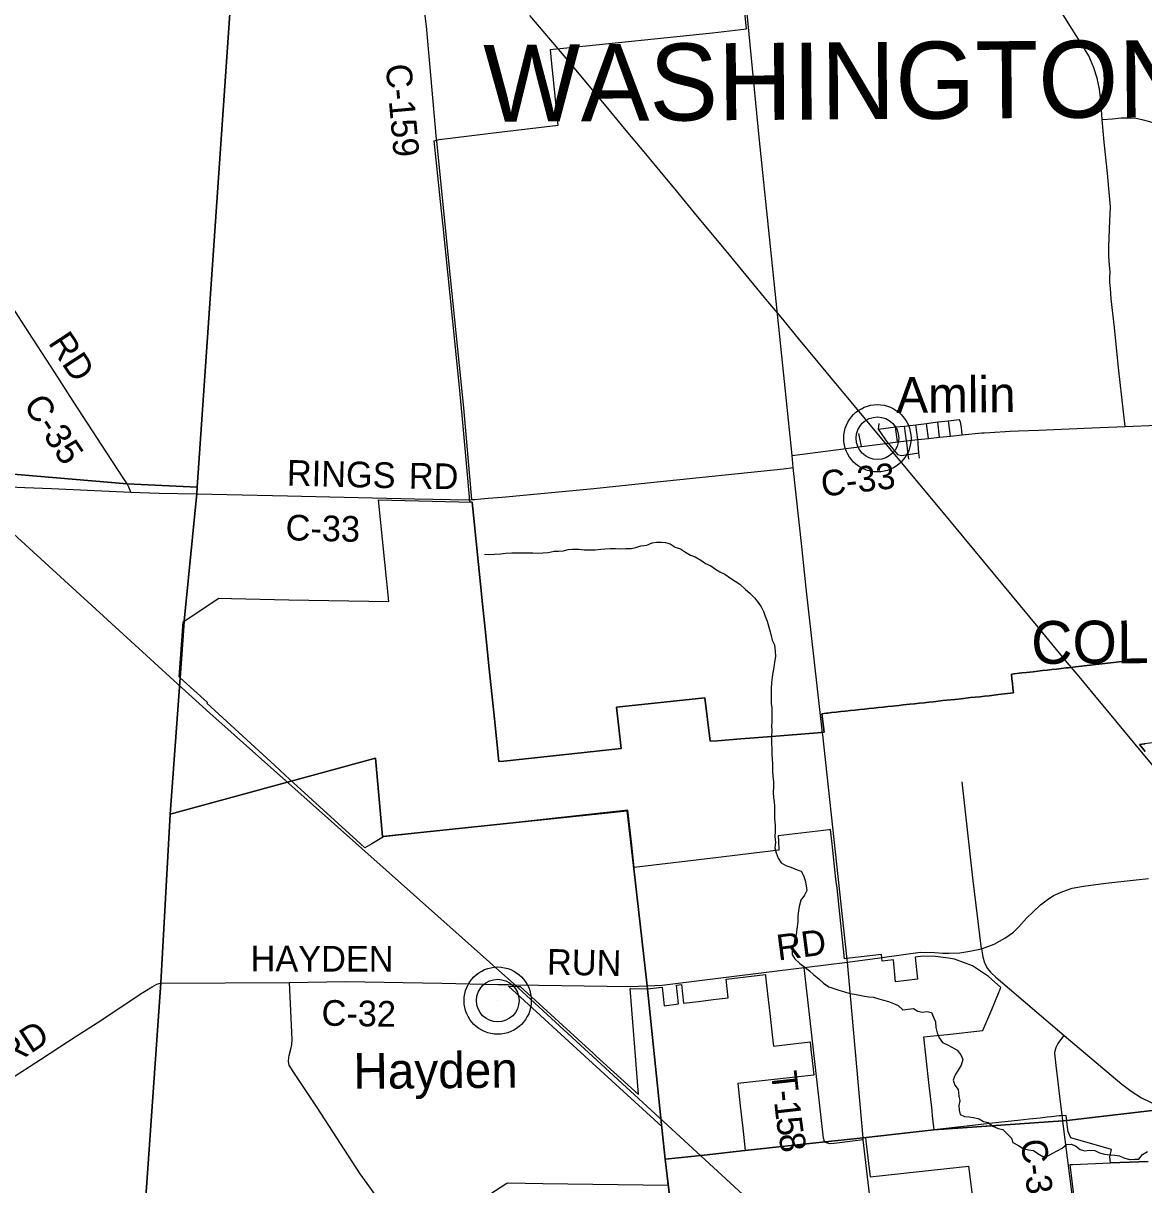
# Model space of a CAD drawing. Extents: x 114843 to 284848, y 317643 to 566895.
# Drawn here: x 145352 to 158450, y 419999 to 433575 of the extents above; entities that cross this region are included whole.
import ezdxf

# ---------------------------------------------------------------- set-up
doc = ezdxf.new("R2010")
doc.units = 0
for name, color, linetype in [('GM_X_City_Street', 7, 'Continuous'), ('GM_X_Corporation', 7, 'Continuous'), ('GM_X_Corporation_Text', 7, 'Continuous'), ('GM_X_County', 7, 'Continuous'), ('GM_X_County_Road', 7, 'Continuous'), ('GM_X_County_Road_Text', 7, 'Continuous'), ('GM_X_Minor_River', 7, 'Continuous'), ('GM_X_Rail_Line', 7, 'Continuous'), ('GM_X_Township', 7, 'Continuous'), ('GM_X_Township_Road', 7, 'Continuous'), ('GM_X_Township_Road_Text', 7, 'Continuous'), ('GM_X_Township_Text', 7, 'Continuous'), ('GM_X_Unincorporated', 7, 'Continuous'), ('GM_X_Unincorporated_Location', 7, 'Continuous'), ('GM_X_Unincorporated_Text', 7, 'Continuous')]:
    doc.layers.add(name, color=color, linetype=linetype)

msp = doc.modelspace()

# ---------------------------------------------------------------- linework, layer by layer
at = {"layer": 'GM_X_City_Street'}
for points in [[(158233, 428861), (158155, 429548), (158106, 430017), (158069, 430354), (158059, 430474), (158054, 430546), (158055, 430600), (158058, 430669), (158051, 430748), (158040, 430854), (158042, 430967), (158054, 431267), (158059, 431429), (158041, 431644), (158026, 431821), (157988, 432183), (157965, 432449), (157946, 432673), (157931, 432805), (157905, 432934), (157867, 433053), (157806, 433193), (157705, 433356), (157613, 433505), (157373, 433894)], [(157965, 432449), (158086, 432459), (158184, 432470), (158255, 432470), (158301, 432469), (158362, 432464), (158427, 432449), (158515, 432427), (158603, 432395), (158736, 432329), (158821, 432262), (158879, 432210), (158886, 432202)], [(156554, 422758), (156452, 423586), (156326, 424708)], [(156554, 422758), (156703, 422811), (156827, 422882), (156926, 422952), (156988, 423012), (157082, 423120), (157155, 423188), (157243, 423271), (157321, 423330), (157396, 423379), (157505, 423428), (157614, 423466), (157745, 423487), (158007, 423522), (158362, 423562), (158504, 423577)]]:
    msp.add_lwpolyline(points, dxfattribs=at)
at = {"layer": 'GM_X_Corporation'}
for points in [[(158460, 426143), (158233, 426117), (157651, 426052), (157570, 426042), (157541, 426039), (157486, 426033), (157431, 426026), (157377, 426020), (157322, 426014), (157267, 426008), (157213, 426002), (157158, 425995), (157078, 425986), (157026, 425981), (156902, 425966), (156908, 425912), (156914, 425857), (156920, 425802), (156926, 425747), (156753, 425727), (156698, 425721), (156643, 425715), (156589, 425709), (156534, 425703), (156479, 425698), (156425, 425692), (156370, 425686), (156315, 425680), (156241, 425672), (156189, 425666), (156100, 425657), (156045, 425651), (155990, 425645), (155936, 425639), (155881, 425633), (155826, 425627), (155771, 425621), (155717, 425616), (155638, 425607), (155587, 425602), (155512, 425594), (155457, 425588), (155403, 425582), (155348, 425576), (155293, 425570), (155239, 425564), (155184, 425558), (155129, 425552), (155075, 425547), (155020, 425541), (154965, 425535), (154910, 425529), (154856, 425523), (154801, 425517), (154756, 425512), (154740, 425511), (154687, 425502), (154714, 425290), (154636, 425282), (154102, 425239), (153739, 425210), (153467, 425188), (153382, 425182), (153320, 425689), (152288, 425580), (152341, 425096), (150969, 424951), (150911, 424945), (150860, 425443), (150800, 426027), (150752, 426494), (150722, 426787), (150600, 427978), (150573, 427979), (150567, 428039), (150482, 428992), (150452, 429321), (150259, 431203), (150230, 431490), (150187, 431904), (150157, 432201), (150215, 432217), (150915, 432300), (151603, 432383), (151581, 432609), (151557, 432841), (151528, 433139), (151515, 433269), (151546, 433272), (151668, 433283), (153407, 433464), (153807, 433508), (153757, 434016)], [(158502, 420272), (158061, 420254), (158052, 420325), (158072, 420411), (157597, 420549), (157565, 420618), (157558, 420673), (157541, 420810), (157479, 420805), (157459, 420803), (157370, 420793), (157320, 420787), (157239, 420779), (157112, 420764), (156977, 420749), (156715, 420721), (156345, 420680), (156000, 420641), (155985, 420771), (155971, 420901), (155957, 421030), (155943, 421160), (155908, 421477), (155880, 421726), (155992, 421738), (156153, 421756), (156569, 421801), (156626, 421939), (156672, 422049), (156778, 422305), (156633, 422432), (156446, 422557), (156237, 422636), (156167, 422647), (156014, 422666), (155873, 422669), (155779, 422658), (155806, 422401), (155546, 422369), (155523, 422627), (155393, 422612), (155383, 422691), (155010, 422646), (154951, 422640), (154864, 423465), (154852, 423570), (154807, 423983), (154788, 424150), (154774, 424149), (154177, 424078), (154180, 424018), (154186, 423908), (153734, 423854), (153477, 423823), (152493, 423708), (152460, 424006), (152419, 424378), (151431, 424268), (150974, 424217), (149562, 424064), (149427, 423984), (149345, 423935), (149293, 423983), (148470, 424734), (148292, 424898), (147497, 425627), (147504, 425635), (147187, 425925), (147174, 425936), (147223, 426577), (147640, 426855), (147788, 426852), (148455, 426836), (149625, 426814), (149504, 428003), (150600, 427978), (150722, 426787), (150752, 426494), (150800, 426027), (150860, 425443), (150911, 424945), (150969, 424951), (152341, 425096), (152288, 425580), (153320, 425689), (153382, 425182), (153467, 425188), (153739, 425210), (154102, 425239), (154636, 425282), (154714, 425290), (154687, 425502), (154740, 425511), (154756, 425512), (154801, 425517), (154856, 425523), (154910, 425529), (154965, 425535), (155020, 425541), (155075, 425547), (155129, 425552), (155184, 425558), (155239, 425564), (155293, 425570), (155348, 425576), (155403, 425582), (155457, 425588), (155512, 425594), (155587, 425602), (155638, 425607), (155717, 425616), (155771, 425621), (155826, 425627), (155881, 425633), (155936, 425639), (155964, 425642), (155990, 425645), (156045, 425651), (156100, 425657), (156189, 425666), (156241, 425672), (156315, 425680), (156370, 425686), (156425, 425692), (156479, 425698), (156534, 425703), (156589, 425709), (156643, 425715), (156698, 425721), (156753, 425727), (156926, 425747), (156920, 425802), (156914, 425857), (156908, 425912), (156902, 425966), (157026, 425981), (157078, 425986), (157158, 425995), (157213, 426002), (157267, 426008), (157322, 426014), (157377, 426020), (157431, 426026), (157486, 426033), (157541, 426039), (157570, 426042), (157651, 426052), (158233, 426117), (158460, 426143)], [(158879, 425207), (158400, 425145), (158468, 425063)], [(158468, 425063), (158400, 425145), (158467, 425154)], [(150354, 419596), (151004, 420017), (151013, 420023), (151425, 420015), (152891, 419993), (152819, 420668), (152817, 420681), (151917, 421502), (151024, 422318), (151135, 422316), (151160, 422316), (152013, 421536), (152050, 421503), (152544, 421052), (152507, 421506), (152446, 422293), (152647, 422289), (152821, 422310), (152844, 422090), (153011, 422113), (152989, 422331), (153048, 422338), (153070, 422120), (153245, 422142), (153418, 422163), (153488, 422171), (153593, 422184), (153570, 422401), (154027, 422456), (154029, 422437), (154052, 422230), (154078, 422001), (154107, 421751), (154121, 421620), (154549, 421668), (154563, 421539), (154565, 421521), (154592, 421278), (154163, 421231), (153703, 421181), (153732, 420920), (153762, 420660), (153791, 420399), (154677, 420496), (154764, 420506), (154925, 420523), (155100, 420544), (155196, 420553), (155205, 420472), (155212, 420413), (155224, 420314), (155250, 420090), (156003, 420173), (156402, 420215), (156459, 419755)], [(157634, 419882), (157590, 420234), (157622, 420235), (158061, 420254), (158502, 420272)]]:
    msp.add_lwpolyline(points, dxfattribs=at)
at = {"layer": 'GM_X_County'}
for points in [[(146658, 418022), (146962, 422359), (147068, 424330), (147186, 425925), (147235, 426587), (147381, 428077), (147386, 428151), (148148, 439230), (148177, 439983), (151138, 439882), (152473, 439858), (155550, 439725), (156053, 439712), (156142, 439709), (156715, 439694), (157545, 439673), (158384, 439650), (158384, 439701), (158353, 446272), (158350, 446686), (158334, 448459), (158404, 452871)], [(140707, 440166), (147260, 440014), (148177, 439983), (148148, 439230), (147386, 428151), (147381, 428077), (147235, 426587), (147186, 425925), (147068, 424330), (146962, 422359), (146658, 418022)]]:
    msp.add_lwpolyline(points, dxfattribs=at)
at = {"layer": 'GM_X_County_Road'}
for p, q in [((154351, 428382), (154338, 428524)), ((154987, 422600), (155366, 422653)), ((146963, 422356), (148463, 422362))]:
    msp.add_line(p, q, dxfattribs=at)
for points in [[(150183, 432219), (150065, 433541), (149938, 434551), (149800, 435349), (149768, 435758), (149550, 438468), (149481, 439320)], [(146567, 428190), (146545, 428225), (146526, 428251), (146331, 428554), (145936, 429157), (145721, 429491), (145366, 430037), (145064, 430505), (144797, 430918), (144567, 431276), (144032, 432101), (143429, 433037), (143149, 433468), (142166, 434991), (142073, 435132), (141863, 435459), (141131, 436585), (140458, 437632), (140407, 437716), (140358, 437803)], [(154338, 428524), (153953, 432244), (153783, 434012), (153716, 434749), (153493, 435495), (153393, 435859), (153264, 436358), (153244, 436435)], [(150596, 428008), (150502, 429081), (150348, 430601), (150185, 432198), (150183, 432219)], [(156586, 428789), (156649, 428793), (156888, 428808), (156987, 428811), (157222, 428819), (157844, 428845), (158233, 428861), (158601, 428875), (158644, 428876), (158689, 428875), (158767, 428869), (159043, 428845), (159121, 428839), (159523, 428805), (159868, 428775), (159950, 428767), (160013, 428766), (160060, 428768), (160463, 428804), (160701, 428825), (161086, 428857), (161867, 428926)], [(154338, 428524), (155149, 428628), (155461, 428665), (155571, 428681), (155676, 428693), (155808, 428708), (155935, 428722), (156061, 428736), (156190, 428749), (156326, 428763), (156555, 428787), (156586, 428789)], [(150700, 428015), (150788, 428022), (150950, 428037), (152021, 428135), (152723, 428211), (154240, 428368), (154351, 428382)], [(154697, 425258), (154694, 425278), (154504, 426972), (154451, 427460), (154351, 428382)], [(141611, 427895), (141926, 427922), (141949, 427922), (142074, 427935), (142172, 427943), (142241, 427946), (143106, 428018), (144362, 428129), (144738, 428163), (144822, 428167), (145001, 428163), (145372, 428148), (145683, 428137), (146608, 428095)], [(146608, 428095), (146596, 428132), (146587, 428152), (146567, 428190)], [(146608, 428095), (146940, 428082), (147383, 428074)], [(147383, 428074), (148441, 428051), (149931, 428016), (150557, 428005), (150596, 428008), (150627, 428009), (150700, 428015)], [(154980, 422652), (154978, 422666), (154697, 425258)], [(155171, 420524), (155169, 420546), (154987, 422600), (154983, 422633), (154980, 422652)], [(155366, 422653), (155836, 422719), (156003, 422713), (156102, 422704), (156176, 422706), (156300, 422711), (156415, 422729), (156554, 422758), (156568, 422664), (156590, 422591), (156624, 422528), (156660, 422482), (156722, 422426), (157518, 421745)], [(152641, 422322), (152647, 422322), (152820, 422333), (153569, 422426), (154479, 422538), (154987, 422600)], [(144135, 420538), (144393, 420703), (145193, 421230), (145555, 421461), (145779, 421611), (145960, 421726), (146217, 421893), (146749, 422246), (146858, 422313), (146914, 422343), (146955, 422356), (146963, 422356)], [(150949, 417965), (150944, 417982), (150930, 418008), (150891, 418068), (150181, 418971), (149524, 419805), (149292, 420128), (148786, 420900), (148506, 421321), (148462, 421397), (148451, 421440), (148455, 421485), (148461, 421510), (148481, 421582), (148493, 421640), (148495, 421698), (148463, 422362)], [(148463, 422362), (149120, 422376), (150245, 422355), (150902, 422339), (150999, 422339)], [(150999, 422339), (151020, 422338), (151105, 422337)], [(151105, 422337), (152445, 422317), (152641, 422322)], [(157430, 421356), (157410, 421537), (157413, 421566), (157420, 421591), (157429, 421616), (157446, 421647), (157518, 421745)], [(157518, 421745), (158193, 421174), (158301, 421094), (158423, 421015), (158527, 420963), (158619, 420922)], [(157499, 420783), (157468, 421029), (157437, 421299), (157430, 421356)], [(157617, 419842), (157613, 419874), (157611, 419885), (157505, 420741), (157499, 420783)], [(155356, 418905), (155352, 418962), (155171, 420524)]]:
    msp.add_lwpolyline(points, dxfattribs=at)
at = {"layer": 'GM_X_Minor_River'}
for points in [[(150745, 427368), (150803, 427366), (150861, 427370), (150935, 427373), (150991, 427381), (151065, 427384), (151121, 427386), (151175, 427384), (151239, 427385), (151307, 427385), (151359, 427381), (151425, 427386), (151489, 427390), (151559, 427403), (151611, 427405), (151667, 427407), (151722, 427424), (151774, 427426), (151846, 427426), (151908, 427421), (151966, 427421), (152038, 427418), (152102, 427426), (152152, 427430), (152212, 427435), (152276, 427435), (152336, 427431), (152394, 427436), (152460, 427436), (152514, 427448), (152572, 427465), (152640, 427473), (152702, 427501), (152754, 427508), (152808, 427510), (152860, 427504), (152914, 427491), (152974, 427451), (153034, 427430), (153092, 427394), (153151, 427359), (153207, 427339), (153271, 427298), (153325, 427260), (153389, 427232), (153442, 427193), (153494, 427163), (153552, 427136), (153620, 427090), (153674, 427055), (153727, 427019), (153793, 426958), (153847, 426914), (153898, 426859), (153942, 426805), (153978, 426755), (154004, 426700), (154023, 426646), (154047, 426588), (154076, 426489), (154096, 426419), (154106, 426365), (154135, 426310), (154141, 426236), (154144, 426174), (154132, 426108), (154124, 426046), (154115, 425987), (154107, 425933), (154097, 425869), (154096, 425797), (154094, 425725), (154093, 425623), (154103, 425572), (154101, 425520), (154102, 425464), (154102, 425410), (154098, 425360), (154103, 425308), (154099, 425239), (154098, 425161), (154102, 425091), (154102, 425031), (154105, 424973), (154111, 424918), (154111, 424832), (154114, 424776), (154120, 424710), (154121, 424648), (154119, 424585), (154123, 424527), (154128, 424475), (154132, 424423), (154132, 424361), (154135, 424276), (154141, 424200), (154140, 424126), (154138, 424068), (154146, 424000), (154139, 423935), (154153, 423877)], [(154153, 423877), (154177, 423817), (154212, 423760), (154266, 423730), (154324, 423712), (154378, 423689), (154444, 423663), (154471, 423612), (154491, 423556), (154503, 423494), (154510, 423438), (154484, 423382), (154442, 423324), (154425, 423268), (154413, 423206), (154407, 423137), (154406, 423075), (154394, 422985), (154385, 422919), (154367, 422859), (154359, 422803), (154340, 422749), (154338, 422691), (154372, 422638), (154431, 422584), (154487, 422543), (154541, 422501), (154592, 422452), (154650, 422404), (154706, 422355), (154770, 422313), (154828, 422294), (154887, 422274), (154939, 422256), (155015, 422235), (155067, 422225), (155127, 422214), (155185, 422202), (155237, 422196), (155289, 422191), (155351, 422173), (155407, 422158), (155467, 422140), (155523, 422116), (155578, 422093), (155632, 422043), (155696, 422050), (155758, 422060), (155810, 422026), (155862, 422015), (155914, 422025), (155970, 422013), (155990, 421958), (156017, 421904), (156019, 421836), (156035, 421773), (156060, 421715), (156098, 421661), (156156, 421634), (156214, 421604), (156267, 421573), (156311, 421517), (156335, 421463), (156316, 421395), (156280, 421337), (156246, 421285), (156223, 421221), (156243, 421164), (156281, 421114), (156288, 421034), (156298, 420978), (156290, 420925), (156293, 420871), (156303, 420819), (156355, 420797), (156409, 420792), (156461, 420784), (156525, 420768), (156576, 420737), (156630, 420725), (156684, 420684), (156746, 420658), (156802, 420646), (156854, 420593), (156905, 420545), (156919, 420494), (156987, 420456), (157039, 420421), (157101, 420405), (157159, 420401), (157212, 420364), (157270, 420330), (157330, 420337), (157380, 420363), (157439, 420397), (157495, 420427), (157547, 420468), (157601, 420474), (157653, 420454), (157707, 420411), (157761, 420397)], [(157761, 420397), (157821, 420403), (157879, 420398), (157932, 420372), (157990, 420357), (158052, 420347), (158110, 420345), (158166, 420338), (158218, 420314), (158282, 420295), (158340, 420299), (158392, 420299), (158436, 420351), (158495, 420388)]]:
    msp.add_lwpolyline(points, dxfattribs=at)
at = {"layer": 'GM_X_Rail_Line'}
for points in [[(128479, 440489), (130998, 439418), (131780, 439073), (132352, 438743), (133270, 438069), (136074, 435852), (137429, 434713), (140276, 432132), (143769, 428946), (146519, 426434), (147203, 425812)], [(159907, 423274), (158330, 425173), (158010, 425557), (157837, 425765), (157693, 425940), (157535, 426128), (157236, 426492), (156029, 427945), (155540, 428536), (155066, 429106), (154739, 429502), (154570, 429704), (154430, 429872), (154230, 430114), (154144, 430218), (154057, 430324), (154018, 430370), (153623, 430848), (153199, 431358), (152953, 431658), (152889, 431734), (152628, 432050), (152401, 432322), (152202, 432563), (151700, 433168), (151275, 433667)], [(147203, 425812), (147532, 425512), (151087, 422349), (154540, 419172), (158440, 415556), (161813, 412533), (168064, 407288)]]:
    msp.add_lwpolyline(points, dxfattribs=at)
at = {"layer": 'GM_X_Township'}
for points in [[(140707, 440166), (147260, 440014), (148177, 439983), (148148, 439230), (147386, 428151), (146566, 428193), (136882, 429015)], [(158583, 420870), (157550, 420750), (157503, 420744), (155996, 420640), (155168, 420549), (154726, 420500), (153787, 420398), (153312, 420346), (152854, 420299), (152815, 420666), (152645, 422325), (152484, 423731), (152411, 424370), (149551, 424070), (149471, 424984), (147068, 424330), (147186, 425925), (147235, 426587), (147381, 428077), (147386, 428151), (148148, 439230)], [(114843, 430764), (117844, 430522), (126052, 429792), (135272, 429152), (136882, 429015), (146566, 428193), (147386, 428151), (147381, 428077), (147235, 426587), (147186, 425925), (147068, 424330), (146962, 422359), (146658, 418022)], [(146658, 418022), (146962, 422359), (147068, 424330), (149471, 424984), (149551, 424070), (152411, 424370), (152484, 423731), (152645, 422325), (152815, 420666), (152854, 420299), (153740, 412913)], [(153740, 412913), (152854, 420299), (153312, 420346), (153787, 420398), (154726, 420500), (155168, 420549), (155996, 420640), (157503, 420744), (157550, 420750), (158583, 420870)]]:
    msp.add_lwpolyline(points, dxfattribs=at)
at = {"layer": 'GM_X_Township_Road'}
for p, q in [((155350, 428832), (155358, 428896)), ((155935, 428722), (155911, 428897)), ((156061, 428736), (156042, 428914)), ((156190, 428749), (156166, 428927)), ((155149, 428628), (155121, 428781)), ((155461, 428665), (155350, 428832)), ((155571, 428681), (155548, 428857))]:
    msp.add_line(p, q, dxfattribs=at)
for points in [[(155350, 428832), (155548, 428857), (155653, 428867), (155785, 428879), (155911, 428897), (156042, 428914), (156166, 428927), (156293, 428944)], [(155814, 428655), (155811, 428686), (155808, 428708), (155785, 428879)], [(156326, 428763), (156319, 428850), (156308, 428917), (156293, 428944)], [(155683, 428642), (155679, 428674), (155676, 428693), (155653, 428867)], [(155461, 428665), (155571, 428533), (155616, 428522), (155697, 428534), (155822, 428554)], [(155704, 428480), (155697, 428534), (155683, 428642)], [(155827, 428492), (155822, 428554), (155814, 428655)], [(154755, 420484), (154740, 420488), (154727, 420498), (154717, 420504), (154706, 420544), (154479, 422538)], [(155171, 420524), (154829, 420482), (154779, 420478), (154755, 420484)]]:
    msp.add_lwpolyline(points, dxfattribs=at)
at = {"layer": 'GM_X_Unincorporated'}
for centre, radius in [((155336, 428724), 393), ((155336, 428724), 249), ((150898, 422151), 393), ((150898, 422151), 249)]:
    msp.add_circle(centre, radius, dxfattribs=at)
at = {"layer": 'GM_X_Unincorporated_Location'}
for p, q in [((155336, 428724), (155336, 428724)), ((150898, 422151), (150898, 422151))]:
    msp.add_line(p, q, dxfattribs=at)

# ---------------------------------------------------------------- texts
at = {"layer": 'GM_X_Corporation_Text'}
msp.add_text('COLUMBUS', height=500, rotation=0.4122, dxfattribs=at).set_placement((157135, 426086))
at = {"layer": 'GM_X_County_Road_Text'}
for s, rotation, p in [('C-159', 275.1069, (149588, 433088)), ('RD', 303.2882, (145636, 429840)), ('C-35', 303.4357, (145346, 429113)), ('RINGS', 358.5792, (148431, 428171)), ('RD', 358.9503, (149857, 428137)), ('C-33', 6.7652, (154695, 428040)), ('C-33', 358.6966, (148416, 427532)), ('RD', 7.3531, (154177, 422619)), ('HAYDEN', 359.9233, (148009, 422492)), ('RUN', 358.873, (151472, 422455)), ('C-32', 359.0723, (148837, 421859)), ('RD', 33.1749, (145196, 421369)), ('C-37', 277.2824, (157011, 420515))]:
    msp.add_text(s, height=300, rotation=rotation, dxfattribs=at).set_placement(p)
at = {"layer": 'GM_X_Township_Road_Text'}
for s, rotation, p in [('T', 276.1257, (154092, 421314)), ('-', 276.1857, (154116, 421091)), ('1', 276.5047, (154129, 420967)), ('5', 277.5314, (154151, 420777)), ('8', 280.2486, (154178, 420579))]:
    msp.add_text(s, height=300, rotation=rotation, dxfattribs=at).set_placement(p)
at = {"layer": 'GM_X_Township_Text'}
msp.add_text('WASHINGTON', height=900, rotation=0.412, dxfattribs=at).set_placement((150734, 432421))
at = {"layer": 'GM_X_Unincorporated_Text'}
for s, rotation, p in [('Amlin', 0.4122, (155558, 429020)), ('Hayden', 0.412, (149212, 421120))]:
    msp.add_text(s, height=417, rotation=rotation, dxfattribs=at).set_placement(p)

doc.saveas('drawing.dxf')
